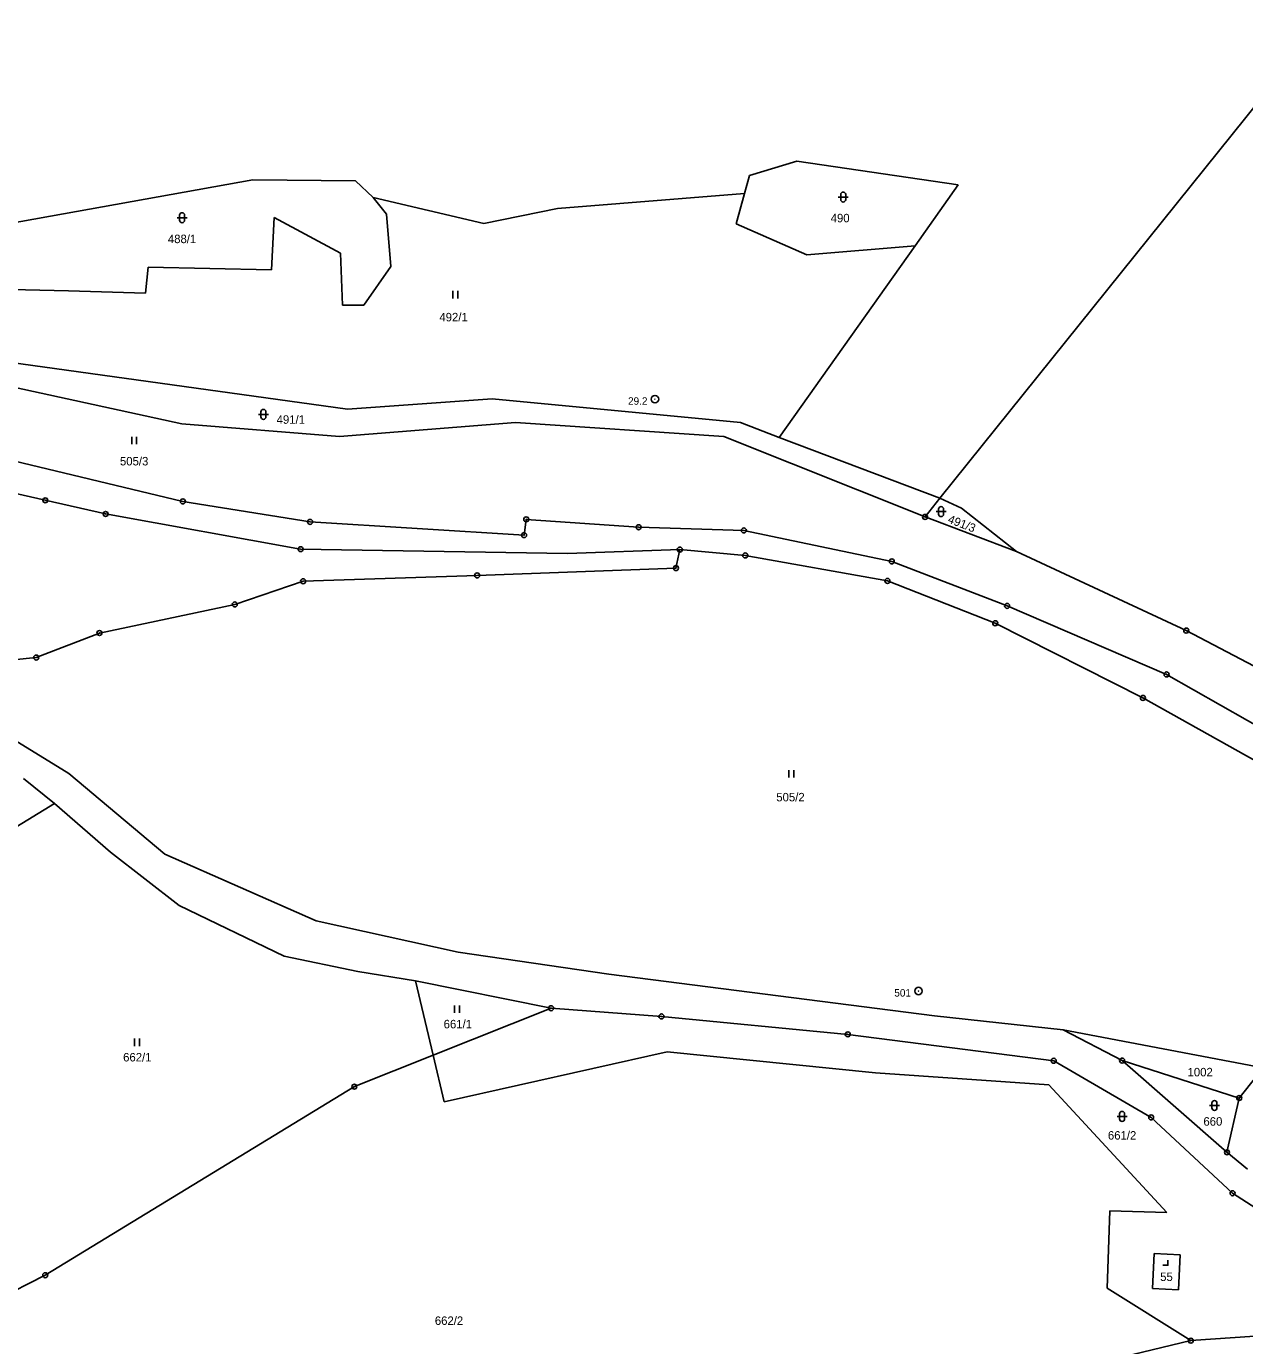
# Model space of a CAD drawing. Extents: x -754970 to -752637, y -970569 to -968179.
# Drawn here: x -753633.5 to -753389.1, y -969384.8 to -969120.1 of the extents above; entities that cross this region are included whole.
import ezdxf
from ezdxf.enums import TextEntityAlignment as Align

# ---------------------------------------------------------------- set-up
doc = ezdxf.new("R2010")
doc.units = 0
doc.header["$LTSCALE"] = 0.68
for name, color, linetype, lineweight in [('1', 7, 'Continuous', 25), ('3', 7, 'Continuous', 25), ('8', 7, 'Continuous', 25)]:
    doc.layers.add(name, color=color, linetype=linetype, lineweight=lineweight)
doc.layers.add('2', color=7, linetype='Continuous')

msp = doc.modelspace()

# ---------------------------------------------------------------- linework, layer by layer
at = {"layer": '1'}
for p, q in [((-753374.24, -969120.09), (-753450.22, -969214.79)), ((-753488.41, -969150.03), (-753478.92, -969147.14)), ((-753478.92, -969147.14), (-753446.55, -969151.89)), ((-753567.44, -969151.09), (-753588.07, -969150.87)), ((-753567.44, -969151.09), (-753563.89, -969154.42)), ((-753488.41, -969150.03), (-753489.44, -969153.63)), ((-753446.55, -969151.89), (-753455.2, -969164.1)), ((-753563.89, -969154.42), (-753541.7, -969159.63)), ((-753563.89, -969154.42), (-753561.23, -969157.75)), ((-753489.44, -969153.63), (-753526.94, -969156.63)), ((-753489.44, -969153.63), (-753491.13, -969159.69)), ((-753541.7, -969159.63), (-753526.94, -969156.63)), ((-753583.75, -969158.41), (-753584.3, -969168.96)), ((-753570.44, -969165.63), (-753583.75, -969158.41)), ((-753561.23, -969157.75), (-753560.34, -969168.29)), ((-753476.89, -969165.96), (-753491.13, -969159.69)), ((-753482.44, -969202.58), (-753455.2, -969164.1)), ((-753455.2, -969164.1), (-753476.89, -969165.96)), ((-753570.1, -969176.06), (-753570.44, -969165.63)), ((-753609.04, -969168.41), (-753609.6, -969173.62)), ((-753584.3, -969168.96), (-753609.04, -969168.41)), ((-753560.34, -969168.29), (-753565.78, -969176.06)), ((-753625.01, -969173.18), (-753639.89, -969172.78)), ((-753609.6, -969173.62), (-753625.01, -969173.18)), ((-753565.78, -969176.06), (-753570.1, -969176.06)), ((-753657.41, -969184.61), (-753569.09, -969196.93)), ((-753602.27, -969199.82), (-753658.53, -969187.62)), ((-753569.09, -969196.93), (-753540.03, -969194.81)), ((-753540.03, -969194.81), (-753490.21, -969199.58)), ((-753535.37, -969199.58), (-753570.65, -969202.37)), ((-753493.54, -969202.36), (-753535.37, -969199.58)), ((-753482.44, -969202.58), (-753490.21, -969199.58)), ((-753570.65, -969202.37), (-753602.27, -969199.82)), ((-753646.47, -969204.82), (-753602.09, -969215.42)), ((-753482.44, -969202.58), (-753450.22, -969214.79)), ((-753665.05, -969206.99), (-753629.68, -969215.2)), ((-753629.68, -969215.2), (-753617.58, -969217.94)), ((-753602.09, -969215.42), (-753576.58, -969219.52)), ((-753450.22, -969214.79), (-753445.9, -969216.8)), ((-753617.58, -969217.94), (-753578.46, -969225)), ((-753434.88, -969225.49), (-753445.9, -969216.8)), ((-753576.58, -969219.52), (-753533.64, -969222.19)), ((-753533.64, -969222.19), (-753533.21, -969219.02)), ((-753533.21, -969219.02), (-753510.66, -969220.6)), ((-753510.66, -969220.6), (-753489.55, -969221.25)), ((-753453.21, -969218.53), (-753434.88, -969225.49)), ((-753489.55, -969221.25), (-753459.87, -969227.45)), ((-753578.46, -969225), (-753524.93, -969225.86)), ((-753524.93, -969225.86), (-753502.41, -969225.09)), ((-753503.17, -969228.79), (-753502.41, -969225.09)), ((-753502.41, -969225.09), (-753489.27, -969226.26)), ((-753434.88, -969225.49), (-753400.81, -969241.34)), ((-753543.06, -969230.26), (-753503.17, -969228.79)), ((-753489.27, -969226.26), (-753460.75, -969231.38)), ((-753459.87, -969227.45), (-753436.74, -969236.38)), ((-753591.68, -969236.1), (-753577.97, -969231.44)), ((-753577.97, -969231.44), (-753543.06, -969230.26)), ((-753460.75, -969231.38), (-753439.12, -969239.87)), ((-753618.84, -969241.83), (-753591.68, -969236.1)), ((-753436.74, -969236.38), (-753404.75, -969250.14)), ((-753631.5, -969246.75), (-753618.84, -969241.83)), ((-753439.12, -969239.87), (-753409.5, -969254.86)), ((-753400.81, -969241.34), (-753365.16, -969260.02)), ((-753636.1, -969247.23), (-753631.5, -969246.75)), ((-753624.98, -969269.99), (-753660.14, -969248.49)), ((-753404.75, -969250.14), (-753372.77, -969268.37)), ((-753409.5, -969254.86), (-753375.54, -969273.84)), ((-753605.68, -969286.21), (-753624.98, -969269.99)), ((-753627.82, -969276.04), (-753616.62, -969285.82)), ((-753616.62, -969285.82), (-753602.85, -969296.5)), ((-753575.32, -969299.6), (-753605.68, -969286.21)), ((-753602.85, -969296.5), (-753581.75, -969306.68)), ((-753546.88, -969305.9), (-753575.32, -969299.6)), ((-753566.96, -969309.76), (-753581.75, -969306.68)), ((-753546.88, -969305.9), (-753516.64, -969310.28)), ((-753555.45, -969311.64), (-753566.96, -969309.76)), ((-753451.28, -969318.65), (-753516.64, -969310.28)), ((-753555.45, -969311.64), (-753551.89, -969326.56)), ((-753555.45, -969311.64), (-753528.23, -969317.12)), ((-753528.23, -969317.12), (-753551.89, -969326.56)), ((-753506.08, -969318.78), (-753528.23, -969317.12)), ((-753468.71, -969322.37), (-753506.08, -969318.78)), ((-753425.53, -969321.47), (-753451.28, -969318.65)), ((-753425.53, -969321.47), (-753385.38, -969329.06)), ((-753413.67, -969327.63), (-753425.53, -969321.47)), ((-753427.4, -969327.67), (-753468.71, -969322.37)), ((-753551.89, -969326.56), (-753567.69, -969332.86)), ((-753551.89, -969326.56), (-753549.65, -969335.93)), ((-753549.65, -969335.93), (-753504.93, -969325.86)), ((-753504.93, -969325.86), (-753463.12, -969330.11)), ((-753407.85, -969339.03), (-753427.4, -969327.67)), ((-753392.64, -969346.04), (-753413.67, -969327.63)), ((-753413.67, -969327.63), (-753390.18, -969335.14)), ((-753385.38, -969329.06), (-753390.18, -969335.14)), ((-753463.12, -969330.11), (-753428.36, -969332.53)), ((-753629.69, -969370.7), (-753567.69, -969332.86)), ((-753428.36, -969332.53), (-753404.69, -969358.15)), ((-753390.18, -969335.14), (-753392.64, -969346.04)), ((-753391.52, -969354.25), (-753407.85, -969339.03)), ((-753392.64, -969346.04), (-753388.53, -969349.39)), ((-753368.03, -969369.39), (-753391.52, -969354.25)), ((-753416.14, -969357.76), (-753416.65, -969373.33)), ((-753404.69, -969358.15), (-753416.14, -969357.76)), ((-753407.26, -969366.37), (-753407.58, -969373.37)), ((-753407.26, -969366.37), (-753402.04, -969366.61)), ((-753402.36, -969373.61), (-753402.04, -969366.61)), ((-753648.04, -969379.97), (-753629.69, -969370.7)), ((-753416.65, -969373.33), (-753399.91, -969383.83)), ((-753407.58, -969373.37), (-753402.36, -969373.61)), ((-753399.91, -969383.83), (-753365.31, -969381.38)), ((-753472.2, -969401.13), (-753399.91, -969383.83))]:
    msp.add_line(p, q, dxfattribs=at)
for points in [[(-753670.95, -969176.18), (-753672.61, -969166.08), (-753588.07, -969150.87)], [(-753450.22, -969214.79), (-753453.21, -969218.53), (-753493.54, -969202.36)], [(-753645.19, -969286.59), (-753627.82, -969276.04), (-753634.09, -969271.01)]]:
    msp.add_lwpolyline(points, dxfattribs=at)
at = {"layer": '3'}
for p, q in [((-753470.621, -969154.341), (-753468.619, -969154.341)), ((-753470.121, -969153.841), (-753470.121, -969154.842)), ((-753469.119, -969154.842), (-753469.119, -969153.841)), ((-753603.251, -969158.481), (-753601.249, -969158.481)), ((-753602.751, -969157.981), (-753602.751, -969158.982)), ((-753601.749, -969158.982), (-753601.749, -969157.981)), ((-753547.941, -969174.68), (-753547.941, -969173.18)), ((-753546.94, -969174.68), (-753546.94, -969173.18)), ((-753586.931, -969197.951), (-753584.929, -969197.951)), ((-753586.431, -969197.451), (-753586.431, -969198.452)), ((-753585.429, -969198.452), (-753585.429, -969197.451)), ((-753612.361, -969203.93), (-753612.361, -969202.43)), ((-753611.36, -969203.93), (-753611.36, -969202.43)), ((-753451.001, -969217.461), (-753448.999, -969217.461)), ((-753450.501, -969216.961), (-753450.501, -969217.962)), ((-753449.499, -969217.962), (-753449.499, -969216.961)), ((-753480.501, -969270.85), (-753480.501, -969269.35)), ((-753479.5, -969270.85), (-753479.5, -969269.35)), ((-753547.631, -969318.05), (-753547.631, -969316.55)), ((-753546.63, -969318.05), (-753546.63, -969316.55)), ((-753611.801, -969324.71), (-753611.801, -969323.21)), ((-753610.8, -969324.71), (-753610.8, -969323.21)), ((-753396.151, -969336.641), (-753394.149, -969336.641)), ((-753395.651, -969336.141), (-753395.651, -969337.142)), ((-753394.649, -969337.142), (-753394.649, -969336.141)), ((-753414.691, -969338.841), (-753412.689, -969338.841)), ((-753414.191, -969338.341), (-753414.191, -969339.342)), ((-753413.189, -969339.342), (-753413.189, -969338.341))]:
    msp.add_line(p, q, dxfattribs=at)
msp.add_lwpolyline([(-753405.501, -969368.69), (-753404.5, -969368.69), (-753404.5, -969367.69)], dxfattribs=at)
for centre, start, end in [((-753469.62, -969153.8409), 0, 180), ((-753469.62, -969154.8409), 180, 359.98789), ((-753602.25, -969157.9809), 0, 180), ((-753602.25, -969158.9809), 180, 359.98789), ((-753585.93, -969197.4509), 0, 180), ((-753585.93, -969198.4509), 180, 359.98789), ((-753450, -969216.9609), 0, 180), ((-753450, -969217.9609), 180, 359.98789), ((-753395.15, -969336.1409), 0, 180), ((-753395.15, -969337.1409), 180, 359.98789), ((-753413.69, -969338.3409), 0, 180), ((-753413.69, -969339.3409), 180, 359.98789)]:
    msp.add_arc(centre, 0.5, start, end, dxfattribs=at)
at = {"layer": '8'}
for centre, radius in [((-753507.39, -969194.8998), 0.75), ((-753507.39, -969194.8998), 0.03), ((-753629.68, -969215.1999), 0.5), ((-753629.68, -969215.1999), 0.0303), ((-753602.09, -969215.4199), 0.5), ((-753602.09, -969215.4199), 0.0303), ((-753617.58, -969217.9399), 0.5), ((-753617.58, -969217.9399), 0.0303), ((-753453.21, -969218.5299), 0.5), ((-753576.58, -969219.5199), 0.5), ((-753576.58, -969219.5199), 0.0303), ((-753533.21, -969219.0199), 0.5), ((-753533.21, -969219.0199), 0.0303), ((-753510.66, -969220.5999), 0.5), ((-753510.66, -969220.5999), 0.0303), ((-753489.55, -969221.2499), 0.5), ((-753453.21, -969218.5299), 0.0303), ((-753533.64, -969222.1899), 0.5), ((-753533.64, -969222.1899), 0.0303), ((-753489.55, -969221.2499), 0.0303), ((-753578.46, -969224.9999), 0.5), ((-753578.46, -969224.9999), 0.0303), ((-753502.41, -969225.0899), 0.5), ((-753502.41, -969225.0899), 0.0303), ((-753489.27, -969226.2599), 0.5), ((-753503.17, -969228.7899), 0.5), ((-753503.17, -969228.7899), 0.0303), ((-753489.27, -969226.2599), 0.0303), ((-753459.87, -969227.4499), 0.5), ((-753459.87, -969227.4499), 0.0303), ((-753577.97, -969231.4399), 0.5), ((-753577.97, -969231.4399), 0.0303), ((-753543.06, -969230.2599), 0.5), ((-753543.06, -969230.2599), 0.0303), ((-753460.75, -969231.3799), 0.5), ((-753460.75, -969231.3799), 0.0303), ((-753591.68, -969236.0999), 0.5), ((-753591.68, -969236.0999), 0.0303), ((-753436.74, -969236.3799), 0.5), ((-753436.74, -969236.3799), 0.0303), ((-753439.12, -969239.8699), 0.5), ((-753618.84, -969241.8299), 0.5), ((-753618.84, -969241.8299), 0.0303), ((-753439.12, -969239.8699), 0.0303), ((-753400.81, -969241.3399), 0.5), ((-753400.81, -969241.3399), 0.0303), ((-753631.5, -969246.7499), 0.5), ((-753631.5, -969246.7499), 0.0303), ((-753404.75, -969250.1399), 0.5), ((-753404.75, -969250.1399), 0.0303), ((-753409.5, -969254.8599), 0.5), ((-753409.5, -969254.8599), 0.0303), ((-753454.53, -969313.6698), 0.75), ((-753454.53, -969313.6698), 0.03), ((-753528.23, -969317.1199), 0.5), ((-753528.23, -969317.1199), 0.0303), ((-753506.08, -969318.7799), 0.5), ((-753506.08, -969318.7799), 0.0303), ((-753468.71, -969322.3699), 0.5), ((-753468.71, -969322.3699), 0.0303), ((-753427.4, -969327.6699), 0.5), ((-753427.4, -969327.6699), 0.0303), ((-753413.67, -969327.6299), 0.5), ((-753413.67, -969327.6299), 0.0303), ((-753567.69, -969332.8599), 0.5), ((-753567.69, -969332.8599), 0.0303), ((-753390.18, -969335.1399), 0.5), ((-753390.18, -969335.1399), 0.0303), ((-753407.85, -969339.0299), 0.5), ((-753407.85, -969339.0299), 0.0303), ((-753392.64, -969346.0399), 0.5), ((-753392.64, -969346.0399), 0.0303), ((-753391.52, -969354.2499), 0.5), ((-753391.52, -969354.2499), 0.0303), ((-753629.69, -969370.6999), 0.5), ((-753629.69, -969370.6999), 0.0303), ((-753399.91, -969383.8299), 0.5), ((-753399.91, -969383.8299), 0.0303)]:
    msp.add_circle(centre, radius, dxfattribs=at)

# ---------------------------------------------------------------- texts
at = {"layer": '2'}
for s, p in [('490', (-753470.239, -969159.405)), ('488/1', (-753602.25, -969163.585)), ('492/1', (-753547.79, -969179.285)), ('491/1', (-753580.44, -969199.835)), ('505/3', (-753611.86, -969208.195)), ('505/2', (-753480.2, -969275.615)), ('661/1', (-753546.93, -969321.155)), ('662/1', (-753611.23, -969327.805)), ('1002', (-753398.02, -969330.795)), ('660', (-753395.469, -969340.695)), ('661/2', (-753413.68, -969343.485)), ('55', (-753404.779, -969371.865)), ('662/2', (-753548.7, -969380.675))]:
    msp.add_text(s, height=1.7, dxfattribs=at).set_placement(p, align=Align.CENTER)
msp.add_text('491/3', height=1.7, rotation=339, dxfattribs=at).set_placement((-753446.1271, -969220.6559), align=Align.CENTER)
at = {"layer": '8'}
for s, p in [('29.2', (-753508.889, -969196.017)), ('501', (-753456.029, -969314.787))]:
    msp.add_text(s, height=1.5, dxfattribs=at).set_placement(p, align=Align.RIGHT)

doc.saveas('drawing.dxf')
